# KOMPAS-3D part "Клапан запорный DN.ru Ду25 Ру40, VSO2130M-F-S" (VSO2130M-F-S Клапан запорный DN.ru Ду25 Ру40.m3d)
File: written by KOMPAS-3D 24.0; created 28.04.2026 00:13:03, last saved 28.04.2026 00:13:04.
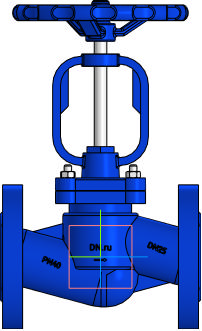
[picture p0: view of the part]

Document properties: Автор: DN.ru; Полное имя файла: C:\Работа\ГОТОВЫЕ ИСХОДНИКИ\VSO2130M-F-S Клапан запорный сальниковый DN.ru Ду15-100 Ру40\DN25\VSO2130M-F-S Клапан запорный DN.ru Ду25 Ру40.m3d

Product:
- Part/product: Клапан запорный DN.ru Ду25 Ру40  | designation VSO2130M-F-S
    Масса: 5.5
    Раздел спецификации: Прочие изделия
    Примечание: D090-01981

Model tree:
1. Операция без истории:1  (labels: SHAPEOBJECT3D_ATTR_BUTT)

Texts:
  VSO2130M-F-S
